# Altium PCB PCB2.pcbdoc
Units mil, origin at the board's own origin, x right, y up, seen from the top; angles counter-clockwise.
Board outline 2952.76 x 3149.61 mil, 2 copper layers (Top Layer, Bottom Layer); 15 components, 30 nets, 98 pads, 14 vias.
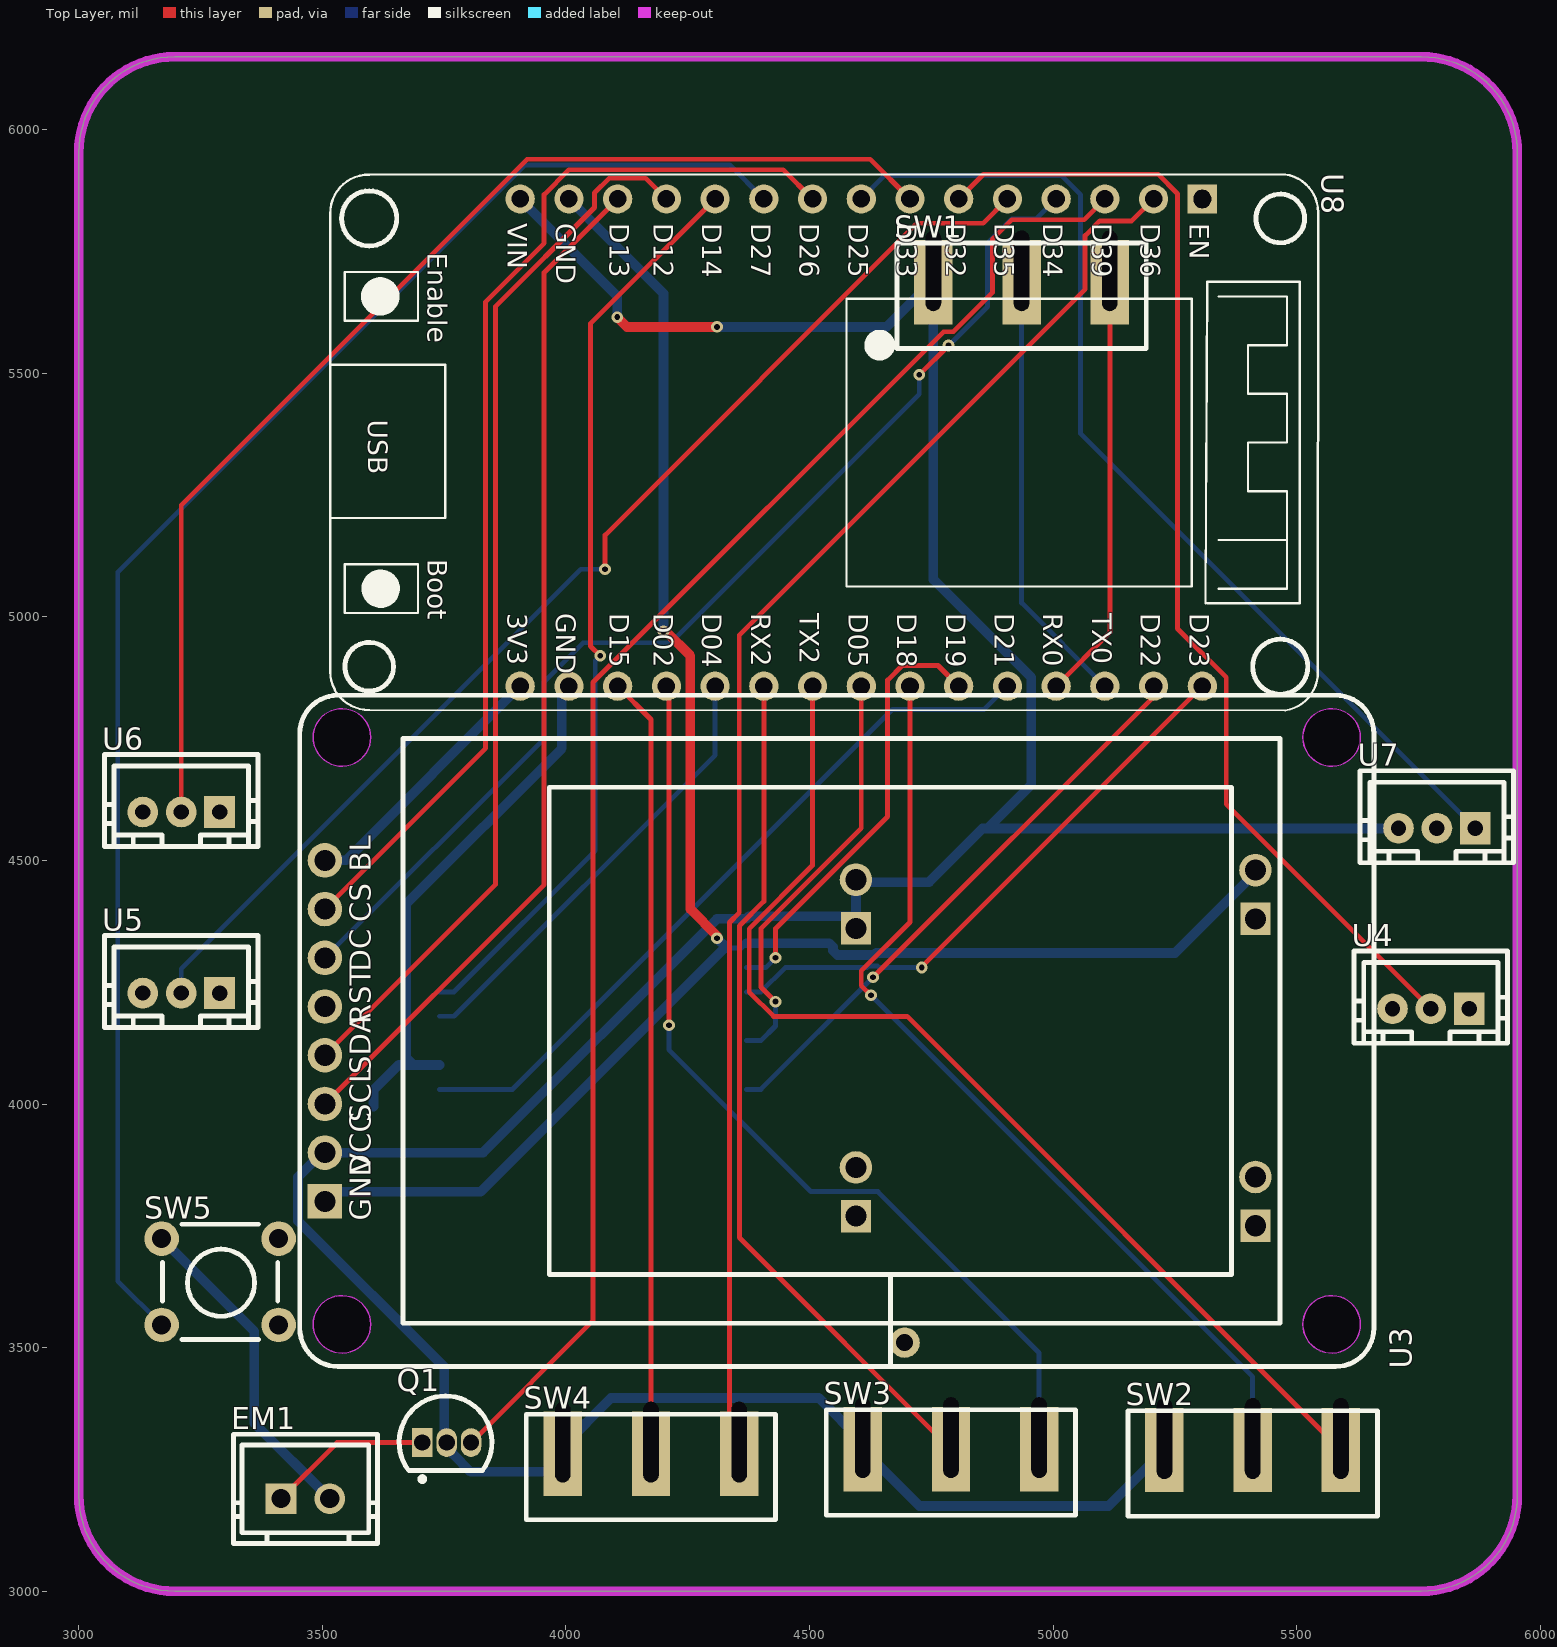
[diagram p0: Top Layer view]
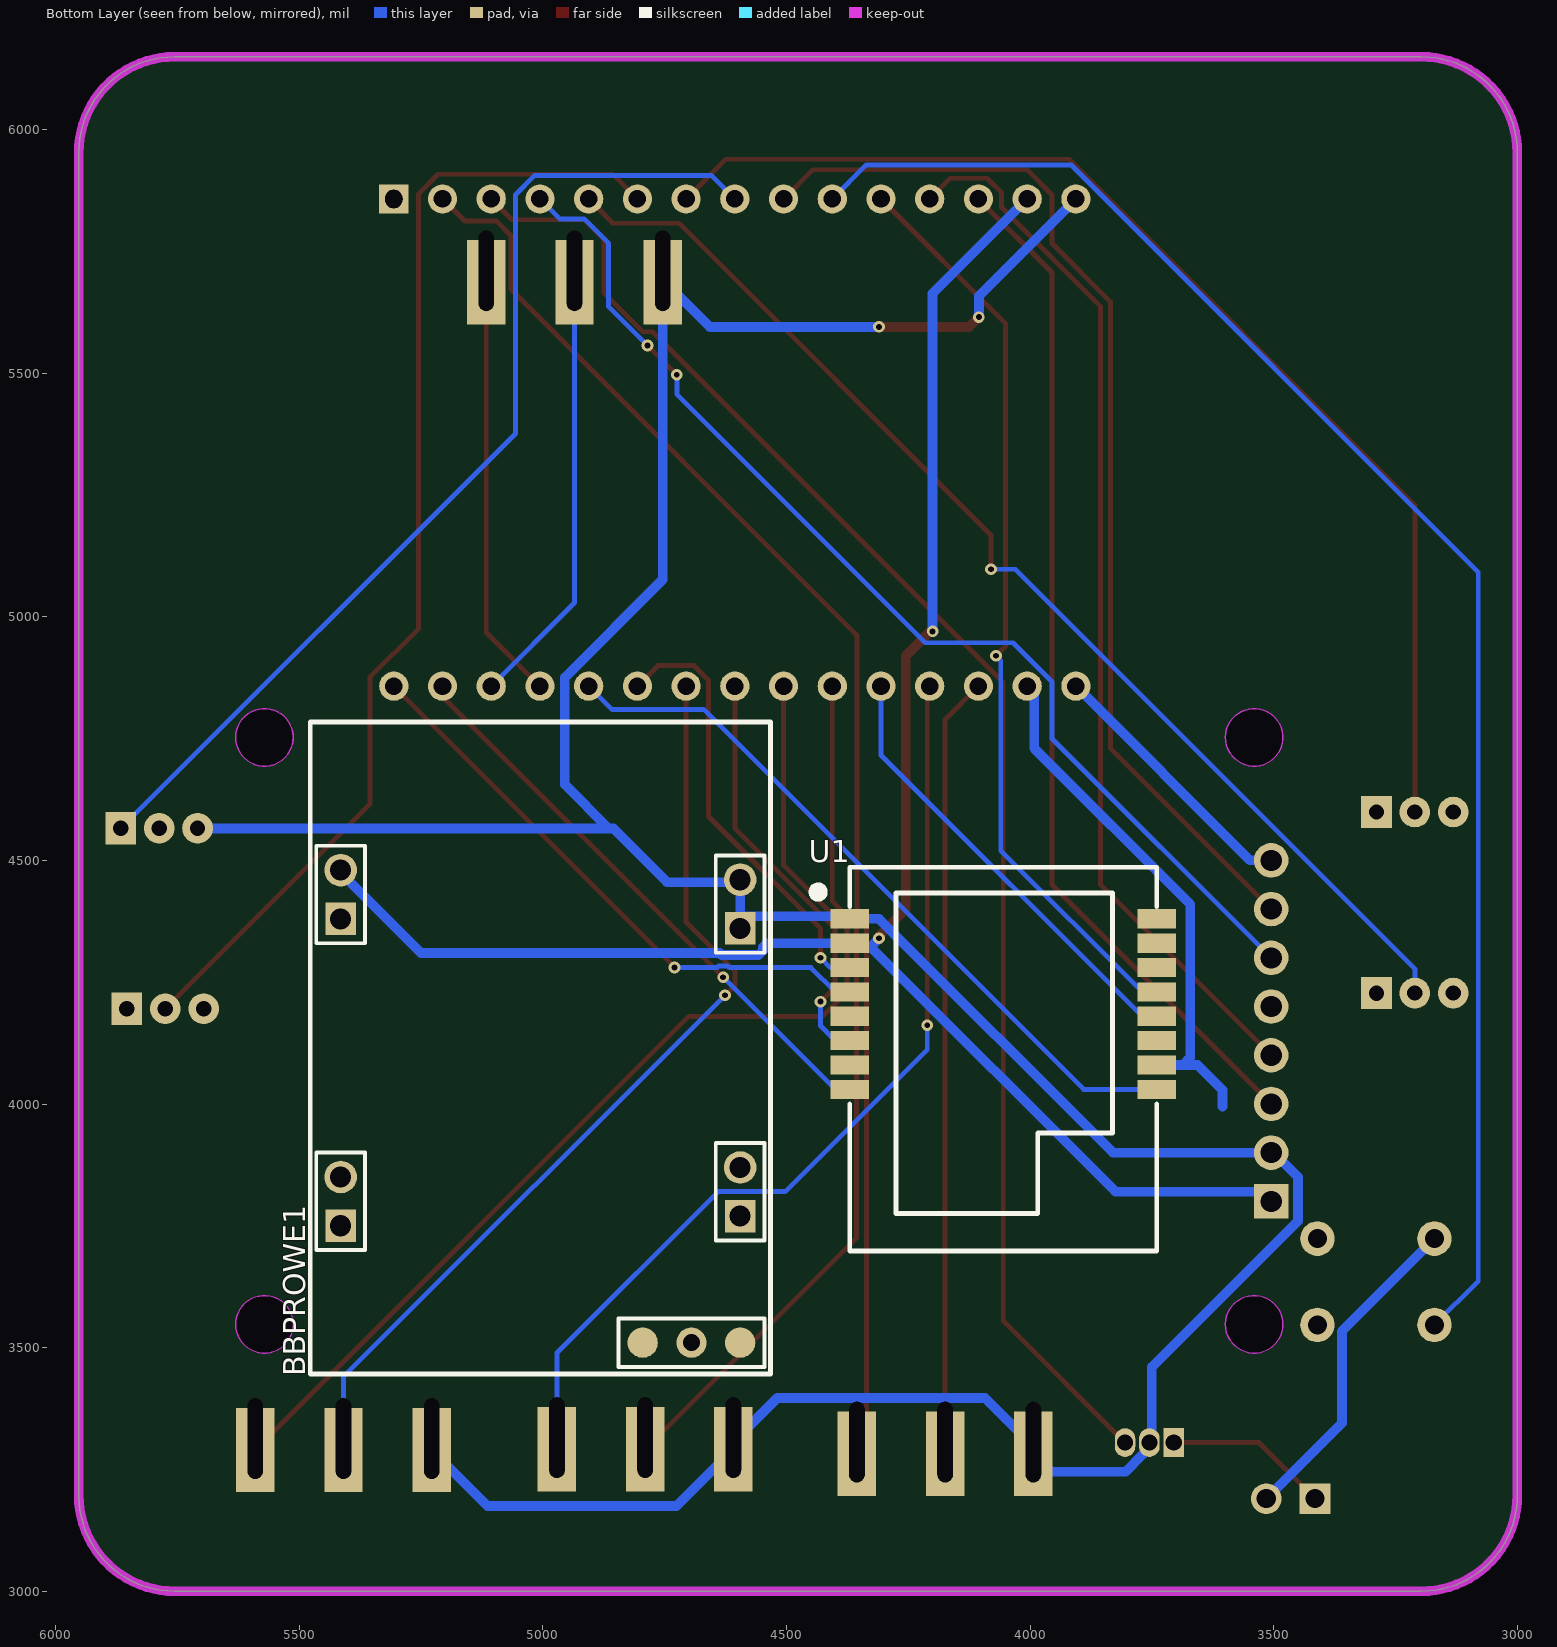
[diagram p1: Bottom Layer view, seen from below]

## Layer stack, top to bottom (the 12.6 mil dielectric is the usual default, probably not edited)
Top Layer: signal copper (thickness not stored)
Dielectric: dielectric 12.6, FR-4, Dk 4.8
Bottom Layer: signal copper (thickness not stored)

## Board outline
5952.76,5952.76 5952.76,3196.85 cw(c5755.91,3196.85) 5755.91,3000 3196.85,3000 cw(c3196.85,3196.85) 3000,3196.85 3000,5952.76 cw(c3196.85,5952.76) 3196.85,6149.61 5755.91,6149.61 cw(c5755.91,5952.76) 5952.76,5952.66

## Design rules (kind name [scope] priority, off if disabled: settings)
BoardOutlineClearance copperThickness1oz [All] p0: genericclearance=10 ignorepadtopadclearanceinfootprint=FALSE except(0: Arc-SplitContinuation Track-SplitContinuation SMDPad-SplitContinuation THPad-SplitContinuation Via-SplitContinuation Fill-SplitContinuation Poly-SplitContinuation Region-SplitContinuation Text-SplitContinuation; 6: Track-CutoutEdge SMDPad-CutoutEdge THPad-CutoutEdge Via-CutoutEdge Region-CutoutEdge; 11.8: Track-OutlineEdge SMDPad-OutlineEdge THPad-OutlineEdge Via-OutlineEdge Fill-OutlineEdge Region-OutlineEdge Poly-OutlineEdge Text-OutlineEdge Fill-CutoutEdge)
BoardOutlineClearance copperThickness2oz [All] p0: genericclearance=10 ignorepadtopadclearanceinfootprint=FALSE except(0: Arc-SplitContinuation Track-SplitContinuation SMDPad-SplitContinuation THPad-SplitContinuation Via-SplitContinuation Fill-SplitContinuation Poly-SplitContinuation Region-SplitContinuation Text-SplitContinuation; 6: Track-CutoutEdge SMDPad-CutoutEdge THPad-CutoutEdge Via-CutoutEdge Region-CutoutEdge; 11.8: Track-OutlineEdge SMDPad-OutlineEdge THPad-OutlineEdge Via-OutlineEdge Fill-OutlineEdge Region-OutlineEdge Poly-OutlineEdge Text-OutlineEdge Fill-CutoutEdge)
Clearance copperThickness1oz [(InNet('$1N1359') OR InNet('$1N1452') OR InNet('$1N2226') OR InNet('$1N1760') OR InNet('$1N1700') OR InNet('$1N1708') OR InNet('$1N1714') OR InNet('$1N1721') OR InNet('$1N1728') OR InNet('$1N1735') OR InNet('$1N1742') OR InNet('$1N1753') OR InNet('$1N1588') OR InNet('$1N2129') OR InNet('$1N1554') OR InNet('$1N1582') OR InNet('$1N1538') OR InNet('$1N1545') OR InNet('$1N1532') OR InNet('$1N1520') OR InNet('$1N1514') OR InNet('$1N1827') OR InNet('$1N1780') OR InNet('$1N1788') OR InNet('$1N1773') OR InNet('$1N1766') OR InNet('$1N1848') OR InNet('$1N1855') OR InNet('$1N1841') OR InNet('$1N1835'))] p1: gap=7 ignorepadtopadclearanceinfootprint=FALSE except(4: Track-Track; 6: Track-SMDPad SMDPad-SMDPad Track-THPad SMDPad-THPad THPad-THPad Track-Via SMDPad-Via THPad-Via Via-Via SMDPad-Fill THPad-Fill Via-Fill Fill-Fill Track-Region SMDPad-Region THPad-Region Via-Region Region-Region Track-Poly SMDPad-Poly THPad-Poly Via-Poly Fill-Poly Region-Poly Poly-Poly Track-Text SMDPad-Text THPad-Text Via-Text Fill-Text Region-Text Poly-Text Text-Text; 6.9: Track-Hole SMDPad-Hole THPad-Hole Via-Hole Fill-Hole Region-Hole Poly-Hole Text-Hole Sheet-Hole; 11.8: Track-Fill Fill-Region Track-Sheet SMDPad-Sheet THPad-Sheet Via-Sheet Fill-Sheet Region-Sheet Poly-Sheet Text-Sheet)
Clearance copperThickness2oz [All] p1: gap=7 ignorepadtopadclearanceinfootprint=FALSE except(6: Track-SMDPad SMDPad-SMDPad Track-THPad SMDPad-THPad THPad-THPad Track-Via SMDPad-Via THPad-Via Via-Via SMDPad-Fill THPad-Fill Via-Fill Fill-Fill Track-Region SMDPad-Region THPad-Region Via-Region Region-Region Track-Poly SMDPad-Poly THPad-Poly Via-Poly Fill-Poly Region-Poly Poly-Poly Track-Text SMDPad-Text THPad-Text Via-Text Fill-Text Region-Text Poly-Text Text-Text; 6.9: Track-Hole SMDPad-Hole THPad-Hole Via-Hole Fill-Hole Region-Hole Poly-Hole Text-Hole Sheet-Hole; 8: Track-Track; 11.8: Track-Fill Fill-Region Track-Sheet SMDPad-Sheet THPad-Sheet Via-Sheet Fill-Sheet Region-Sheet Poly-Sheet Text-Sheet)
DiffPairsRouting differentialPair [All] p1: maxuncoupledlength=10 minlimit=6 maxlimit=6 mostfreqgap=6 toplayer_minwidth=5 toplayer_prefwidth=10 toplayer_maxwidth=100 bottomlayer_minwidth=5 bottomlayer_prefwidth=10 bottomlayer_maxwidth=100
PasteMaskExpansion pasteMaskExpansion [All] p1: expansion=0
PlaneConnect innerPlane [All] p1: planeconnectstyle=Relief reliefexpansion=20 reliefentries=4 reliefconductorwidth=10 reliefairgap=10
PolygonConnect copperRegion [All] p1: connectstyle=Relief reliefentries=4 reliefconductorwidth=10 polygonreliefangle="90 Angle" airgapwidth=10
RoutingVias viaSize [All] p1: viastyle="Through Hole" holewidth=12.0078 minholewidth=11.811 maxholewidth=248.0314 width=24.0158 minwidth=19.685 maxwidth=393.7008
SolderMaskExpansion solderMaskExpansion [All] p1: useseparateexpansions=TRUE expansion=2 expansionbottom=2
Width copperThickness1oz [All] p1: maxlimit=100 minlimit=5 preferedwidth=10
Width copperThickness2oz [All] p1: maxlimit=100 minlimit=8 preferedwidth=10

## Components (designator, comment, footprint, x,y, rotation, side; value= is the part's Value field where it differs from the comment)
BBPROWE1 "TPS63020_Module" TPS63020_MODULE_PCB 5005.2,4115.16 r90 bottom
EM1 "GVI AC Fan" CONN-TH_2P-P2.54-V 3465.2,3190.16 r0 top
Q1 "3DD13003A" TO-92-3_L4.8-W3.7-P1.27-L 3755.2,3305.16 r0 top
SW1 "3_Position_Toggle_Switch" 3_Pin_Toggle_Switch_Footprint 4935.2,5600.16 r0 top
SW2 "3_Position_Toggle_Switch" 3_Pin_Toggle_Switch_Footprint 5409.49,3203.23 r0 top
SW3 "3_Position_Toggle_Switch" 3_Pin_Toggle_Switch_Footprint 4790.2,3205.16 r0 top
SW4 "3_Position_Toggle_Switch" 3_Pin_Toggle_Switch_Footprint 4174.49,3195.99 r0 top
SW5 "Button-6x6x6mm" SW-TH_4PIN-L6.00-W6.00 3290.2,3635.16 r0 top
U1 "E28-2G4M27SX" WIRELM-SMD_E28-2G4M27SX 4055.2,4205.16 r180 bottom
U3 "WeAct 1.8inch TFT Display ST7735" "WeAct 1.8 inch TFT ST7735S" 3505.2,3800.16 r90 top
U4 "JST-PH_3-PIN_2.0MM" "JST PH 3-PIN 2.0MM TOP ENTRY" 5617.82,4124.8 r0 top
U5 "JST-PH_3-PIN_2.0MM" "JST PH 3-PIN 2.0MM TOP ENTRY" 3052.82,4156.89 r0 top
U6 "JST-PH_3-PIN_2.0MM" "JST PH 3-PIN 2.0MM TOP ENTRY" 3052.82,4528.46 r0 top
U7 "JST-PH_3-PIN_2.0MM" "JST PH 3-PIN 2.0MM TOP ENTRY" 5630.2,4495.16 r0 top
U8 "ESP32 DEVKIT 30PIN" "ESP32 DEVKIT 30P" 5465.2,5830.16 r270 top

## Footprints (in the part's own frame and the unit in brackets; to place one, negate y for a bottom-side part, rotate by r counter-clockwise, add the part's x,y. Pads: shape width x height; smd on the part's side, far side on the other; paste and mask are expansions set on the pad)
3_Pin_Toggle_Switch_Footprint [mm]
  rect 2x4.4 hole 0.8 slot 4.2 at 90 deg copper offset 0,-0.6: 1(-4.6,2.8) 2(0,2.8) 3(4.6,2.8)
  silkscreen extent -6.5,-1.25 6.5,4.25
CONN-TH_2P-P2.54-V [mm]
  rect 1.6x1.6 hole 1: L(-1.27,0)
  round 1.6 hole 1: N(1.27,0)
  silkscreen extent -3.75,-2.34 3.75,3.36
"ESP32 DEVKIT 30P" [mil]
  rect 60x60 hole 36 slot 37.8 at 0 deg copper offset 0.01,-0.01: 1(-27.56,-159.05)
  round 60 hole 36 copper offset 0.01,-0.02: 2(-27.56,-259.05) 3(-27.56,-359.05) 4(-27.56,-459.05) 5(-27.56,-559.05) 6(-27.56,-659.05) 7(-27.56,-759.05) 8(-27.56,-859.05) 9(-27.56,-959.05) 10(-27.56,-1059.05) 11(-27.56,-1159.05) 12(-27.56,-1259.05) 13(-27.56,-1359.05) 16(972.44,-159.05) 17(972.44,-259.05) 18(972.44,-359.05) 19(972.44,-459.05) 20(972.44,-559.05) 21(972.44,-659.05) 22(972.44,-759.05) 23(972.44,-859.05) 24(972.44,-959.05) 25(972.44,-1059.05) 26(972.44,-1159.05) 27(972.44,-1259.05) 28(972.44,-1359.05)
  round 60 hole 36 copper offset 0.01,-0.01: 14(-27.56,-1459.05) 15(-27.56,-1559.05) 29(972.44,-1459.05) 30(972.44,-1559.05)
  silkscreen extent -78,-1949 1022,79
"JST PH 3-PIN 2.0MM TOP ENTRY" [mm]
  rect 1.6x1.676 hole 0.8: 1(6,1.8)
  round 1.6 hole 0.8: 2(4,1.801) 3(1.999,1.801)
  silkscreen extent 0,0 8,4.8
SW-TH_4PIN-L6.00-W6.00 [mm]
  round 1.8 hole 1: 1(-3.05,2.25) 2(3.05,2.25) 3(-3.05,-2.25) 4(3.05,-2.25)
  silkscreen extent -3,-3 3,3
TO-92-3_L4.8-W3.7-P1.27-L [mm]
  rect 1.07x1.5 hole 0.85: 1(-1.27,0)
  oval 1.07x1.5 hole 0.85: 2(0,0) 3(1.27,0)
  silkscreen extent -2.48,-2.03 2.36,2.43
TPS63020_MODULE_PCB [mil]
  rect 66.93x62 hole 43.31: 1(-364.96,410) 3(264.96,410) 5(-345.28,-410) 7(245.28,-410)
  round 66.93 hole 43.31: 2(-264.96,410) 4(364.96,410) 6(-245.28,-410) 8(345.28,-410)
  round 62 smd: 9(-605,-410) 11(-605,-210)
  round 62 hole 35: 10(-605,-310)
  silkscreen extent -669,-472 669,472
"WeAct 1.8 inch TFT ST7735S" [mm]
  rect 1.8x1.8 hole 1.1: 1(0,0)
  round 1.8 hole 1.1: 2(2.54,0) 3(5.08,0) 4(7.62,0) 5(10.16,0) 6(12.7,0) 7(15.24,0) 8(17.78,0)
  Board Outline Layer circle w0.025: c-6.41,-0.889 r1.5
  Board Outline Layer circle w0.025: c24.19,-0.889 r1.5
  Board Outline Layer circle w0.025: c-6.41,-52.489 r1.5
  Board Outline Layer circle w0.025: c24.19,-52.489 r1.5
  Board Outline Layer region: -6.41,-2.389 -7.061,-2.24 -7.583,-1.824 -7.872,-1.223 -7.872,-0.555 -7.583,0.046 -7.061,0.462 -6.41,0.611 -6.41,0.611 -5.759,0.462 -5.237,0.046 -4.948,-0.555 -4.948,-1.223 -5.237,-1.824 -5.759,-2.24 -6.41,-2.389
  Board Outline Layer region: 24.19,-2.389 23.539,-2.24 23.017,-1.824 22.728,-1.223 22.728,-0.555 23.017,0.046 23.539,0.462 24.19,0.611 24.19,0.611 24.841,0.462 25.363,0.046 25.652,-0.555 25.652,-1.223 25.363,-1.824 24.841,-2.24 24.19,-2.389
  Board Outline Layer region: -6.41,-53.989 -7.061,-53.84 -7.583,-53.424 -7.872,-52.823 -7.872,-52.155 -7.583,-51.554 -7.061,-51.138 -6.41,-50.989 -6.41,-50.989 -5.759,-51.138 -5.237,-51.554 -4.948,-52.155 -4.948,-52.823 -5.237,-53.424 -5.759,-53.84 -6.41,-53.989
  Board Outline Layer region: 24.19,-53.989 23.539,-53.84 23.017,-53.424 22.728,-52.823 22.728,-52.155 23.017,-51.554 23.539,-51.138 24.19,-50.989 24.19,-50.989 24.841,-51.138 25.363,-51.554 25.652,-52.155 25.652,-52.823 25.363,-53.424 24.841,-53.84 24.19,-53.989
  Multi-Layer board cut-out: -6.41,-2.389 -7.061,-2.24 -7.583,-1.824 -7.872,-1.223 -7.872,-0.555 -7.583,0.046 -7.061,0.462 -6.41,0.611 -6.41,0.611 -5.759,0.462 -5.237,0.046 -4.948,-0.555 -4.948,-1.223 -5.237,-1.824 -5.759,-2.24 -6.41,-2.389
  Multi-Layer board cut-out: 24.19,-2.389 23.539,-2.24 23.017,-1.824 22.728,-1.223 22.728,-0.555 23.017,0.046 23.539,0.462 24.19,0.611 24.19,0.611 24.841,0.462 25.363,0.046 25.652,-0.555 25.652,-1.223 25.363,-1.824 24.841,-2.24 24.19,-2.389
  Multi-Layer board cut-out: -6.41,-53.989 -7.061,-53.84 -7.583,-53.424 -7.872,-52.823 -7.872,-52.155 -7.583,-51.554 -7.061,-51.138 -6.41,-50.989 -6.41,-50.989 -5.759,-51.138 -5.237,-51.554 -4.948,-52.155 -4.948,-52.823 -5.237,-53.424 -5.759,-53.84 -6.41,-53.989
  Multi-Layer board cut-out: 24.19,-53.989 23.539,-53.84 23.017,-53.424 22.728,-52.823 22.728,-52.155 23.017,-51.554 23.539,-51.138 24.19,-50.989 24.19,-50.989 24.841,-51.138 25.363,-51.554 25.652,-52.155 25.652,-52.823 25.363,-53.424 24.841,-53.84 24.19,-53.989
  silkscreen extent -8.61,-54.69 26.39,1.31
WIRELM-SMD_E28-2G4M27SX [mm]
  rect 2x1 smd: 1(-8,4.445) 2(-8,3.175) 3(-8,1.905) 4(-8,0.635) 5(-8,-0.635) 6(-8,-1.905) 7(-8,-3.175) 8(-8,-4.445) 9(8,-4.445) 10(8,-3.175) 11(8,-1.905) 12(8,-0.635) 13(8,0.635) 14(8,1.905) 15(8,3.175) 16(8,4.445)
  silkscreen extent -9.9,-12.86 8,7.14

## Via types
v1: diameter 24.02, hole 12.01, Top Layer to Bottom Layer, 14 vias

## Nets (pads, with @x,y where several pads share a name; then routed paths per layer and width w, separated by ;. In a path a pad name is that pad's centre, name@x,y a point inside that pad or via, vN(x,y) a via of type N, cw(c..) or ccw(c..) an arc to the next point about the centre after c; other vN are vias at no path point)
$1N1359: BBPROWE1.4 U1.2 U3.1 U8.14 | length 3888.3
  Top Layer w20: v1(4200.16,4970.16) 4205.16,4970.16 4255.16,4920.16 4255.16,4400.16 4310.16,4345.16 v1(4310.16,4340.16)
  Bottom Layer w10: 4330.16,4320.16 4360.16,4320.16 U1.2
  Bottom Layer w20: U3.1 3525.2,3820.16 3825.16,3820.16 4325.16,4320.16 4330.16,4320.16 v1(4310.16,4340.16) ; U8.14 4200.16,5663.68 v1(4200.16,4970.16) ; U1.2 4540.24,4330.16 4548.21,4322.18 4548.21,4315.35 4557.58,4305.99 4632.82,4305.99 4636.99,4310.16 5250.24,4310.16 BBPROWE1.4@5415.2,4475.12
$1N1452: BBPROWE1.7 BBPROWE1.8 Q1.2 SW1.1 SW2.1 SW3.1 SW4.1 U1.1 U3.2 U7.3 U8.15 | length 7290.8
  Top Layer w20: v1(4105.2,5615.16) 4125.2,5595.16 v1(4310.2,5595.16)
  Bottom Layer w10: BBPROWE1.7@4595.2,4355.44 BBPROWE1.7@4595.2,4385.44
  Bottom Layer w20: U8.15 4105.2,5658.64 v1(4105.2,5615.16) ; v1(4310.2,5595.16) 4657.48,5595.16 4754.09,5691.77 4754.09,5076.54 4955.2,4875.44 4955.2,4655.44 4865.2,4565.44 ; SW2.1@5228.38,3289.85 5113.69,3175.16 4725.71,3175.16 4609.09,3291.77 4609.09,3306.77 4519.09,3396.77 4092.55,3396.77 3993.38,3297.61 3993.38,3282.61 3955.93,3245.16 3804.34,3245.16 3768.15,3281.35 3768.15,3282.2 3755.2,3295.16 Q1.2 3750.2,3310.16 3750.2,3460.16 3450.2,3760.16 3450.2,3850.16 3500.2,3900.16 U3.2 3830.16,3900.16 4310.16,4380.16 U1.1 4375.44,4385.44 4595.2,4385.44 4595.2,4455.44 4745.2,4455.44 4855.2,4565.44 4865.2,4565.44 ; U7.3 5708.28,4565.44 4865.2,4565.44
$1N1514: U1.3 U8.21 | length 909.5
  Top Layer w10: v1(4430.16,4300.16) 4430.16,4360.16 4660.16,4590.16 4660.16,4870.16 4690.16,4900.16 4763.68,4900.16 U8.21
  Bottom Layer w10: U1.3 4410.16,4280.16 v1(4430.16,4300.16)
$1N1520: U1.4 U8.16 | length 1199.3
  Top Layer w10: v1(4730.16,4280.16) 4730.16,4281.73 U8.16
  Bottom Layer w10: U1.4 4400.16,4230.16 4450.16,4280.16 4617.64,4280.16 4620.63,4283.15 4639.68,4283.15 4642.67,4280.16 v1(4730.16,4280.16)
$1N1532: U1.6 U8.23 | length 867.7
  Top Layer w10: v1(4430.16,4210.16) 4400.16,4240.16 4400.16,4360.16 4606.13,4566.13 U8.23
  Bottom Layer w10: U1.6 4400.16,4130.16 4430.16,4160.16 v1(4430.16,4210.16)
$1N1538: U1.9 U8.20 | length 1508.7
  Bottom Layer w10: U1.9 3890.24,4030.16 4670.24,4810.16 4858.58,4810.16 U8.20
$1N1545: U1.8 U8.17 | length 1191.4
  Top Layer w10: v1(4630.16,4260.16) 5206.13,4836.13 U8.17
  Bottom Layer w10: U1.8 4400.16,4030.16 v1(4630.16,4260.16)
$1N1554: U1.13 U8.11 | length 1896.1
  Top Layer w10: v1(4070.24,4920.16) 4050.24,4940.16 4050.24,5601.81 U8.11
  Bottom Layer w10: U1.13 3770.24,4230.16 4060.24,4520.16 4060.24,4910.16 v1(4070.24,4920.16)
$1N1582: U1.12 U8.26 | length 929.5
  Bottom Layer w10: U1.12 3770.24,4180.16 4306.13,4716.05 U8.26
$1N1588: EM1.N SW5.1 U1.10 U8.29 | length 1788.8
  Bottom Layer w20: SW5.1 3360.12,3533.74 3360.12,3345.24 EM1.N ; 3605.2,3995.16 3605.2,4028.82 3656.54,4080.16 3686.54,4080.16 ; U1.10 3686.54,4080.16 ; U8.29 3991.54,4843.11 3991.54,4730.16 3671.54,4410.16 3671.54,4095.16 3686.54,4080.16
$1N1700: SW1.2 U8.18 | length 904.9
  Bottom Layer w10: SW1.2@4935.2,5691.77 4935.2,5028.64 U8.18
$1N1708: SW1.3 U8.19 | length 879.7
  Top Layer w10: U8.19 5116.3,4967.87 SW1.3@5116.3,5691.77
$1N1714: SW2.2 U8.22 | length 1942
  Top Layer w10: v1(4626.13,4223.2) 4606.13,4243.2 4606.13,4273.2 4706.13,4373.2 U8.22
  Bottom Layer w10: v1(4626.13,4223.2) 5409.49,3439.85 SW2.2@5409.49,3289.85
$1N1721: SW2.3 U8.24 | length 2285.5
  Top Layer w10: U8.24 4506.13,4489.85 4376.13,4359.85 4376.13,4229.85 4426.13,4179.85 4700.59,4179.85 SW2.3@5590.59,3289.85
$1N1728: SW3.2 U8.25 | length 1766.4
  Top Layer w10: U8.25 4406.13,4415.84 4356.13,4365.84 4356.13,3725.84 SW3.2@4790.2,3291.77
$1N1735: SW3.3 U8.27 | length 1963.3
  Top Layer w10: U8.27 4211.3,4852.54 v1(4211.3,4161.77)
  Bottom Layer w10: v1(4211.3,4161.77) 4211.3,4111.77 4502.91,3820.16 4640.2,3820.16 4971.3,3489.06 SW3.3@4971.3,3291.77
$1N1742: SW4.2 U8.28 | length 1603.4
  Top Layer w10: U8.28 4174.49,4789.35 SW4.2@4174.49,3282.61
$1N1753: SW4.3 U8.2 | length 2982.3
  Top Layer w10: SW4.3@4355.59,3282.61 4335.59,3302.61 4335.59,4372.61 4355.59,4392.61 4355.59,4962.61 5065.59,5672.61 5065.59,5782.61 5095.59,5812.61 5161.03,5812.61 U8.2
$1N1760: Q1.3 U8.3 | length 3190.1
  Top Layer w10: Q1.3 4055.2,3555.16 4055.2,4865.16 4775.2,5585.16 4795.2,5585.16 4875.2,5665.16 4875.2,5775.16 4915.2,5815.16 5063.58,5815.16 U8.3
$1N1766: U3.3 U8.13 | length 2106.5
  Top Layer w10: U3.3 3955.2,4450.16 3955.2,5706.77 U8.13
$1N1773: U3.4 U8.12 | length 2176.8
  Top Layer w10: U3.4 3855.2,4450.16 3855.2,5636.77 4058.58,5840.16 4058.58,5870.16 4088.58,5900.16 4163.68,5900.16 U8.12
$1N1780: U3.7 U8.9 | length 2249.9
  Top Layer w10: U3.7 3835.2,4730.16 3835.2,5646.77 3955.2,5766.77 3955.2,5866.77 4006.13,5917.71 4446.13,5917.71 U8.9
$1N1788: U3.6 U8.4 | length 2314
  Top Layer w10: v1(4725.2,5496.77) v1(4785.2,5556.77)
  Bottom Layer w10: U3.6 3955.2,4750.16 3955.2,4866.77 4035.2,4946.77 4215.2,4946.77 4725.2,5456.77 v1(4725.2,5496.77) ; v1(4785.2,5556.77) 4865.2,5636.77 4865.2,5766.77 4915.2,5816.77 4965.2,5816.77 U8.4
$1N1827: U3.8 U8.30 | length 549
  Bottom Layer w20: U3.8 3548.58,4500.16 U8.30
$1N1835: U7.1 U8.8 | length 2122.4
  Bottom Layer w10: U8.8 4654.45,5906.03 5016.42,5906.03 5056.42,5866.03 5056.42,5376.03 U7.1
$1N1841: U6.2 U8.7 | length 2453.7
  Top Layer w10: U6.2 3210.32,5229.36 3920.32,5939.36 4624.48,5939.36 U8.7
$1N1848: U4.2 U8.6 | length 2375
  Top Layer w10: U8.6 4856.95,5908.52 5215.32,5908.52 5255.32,5868.52 5255.32,4975.7 5355.32,4875.7 5355.32,4615.7 U4.2
$1N1855: U5.2 U8.5 | length 2441.2
  Top Layer w10: v1(4080.32,5097.78) 4080.32,5167.78 4720.32,5807.78 4856.21,5807.78 U8.5
  Bottom Layer w10: U5.2 3210.32,4277.78 4030.32,5097.78 v1(4080.32,5097.78)
$1N2129: SW5.3 U8.10 | length 3283.7
  Bottom Layer w10: SW5.3 3080.12,3636.58 3080.12,5091.69 3916.13,5927.71 4336.13,5927.71 U8.10
$1N2226: EM1.L Q1.1 | length 337.6
  Top Layer w10: EM1.L 3530.2,3305.16 Q1.1
pads on no net: BBPROWE1.1 BBPROWE1.2 BBPROWE1.3 BBPROWE1.5 BBPROWE1.6 BBPROWE1.9 BBPROWE1.10 BBPROWE1.11 SW5.2 SW5.4 U1.5 U1.7 U1.11 U1.14 U1.15 U1.16 U3.5 U4.1 U4.3 U5.1 U5.3 U6.1 U6.3 U7.2 U8.1

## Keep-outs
Board Outline Layer:
  lines w20: 5952.76,5952.66 ccw(c5755.91,5952.76) 5755.91,6149.61 3196.85,6149.61 ccw(c3196.85,5952.76) 3000,5952.76 3000,3196.85 ccw(c3196.85,3196.85) 3196.85,3000 5755.91,3000 ccw(c5755.91,3196.85) 5952.76,3196.85 5952.76,5952.76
